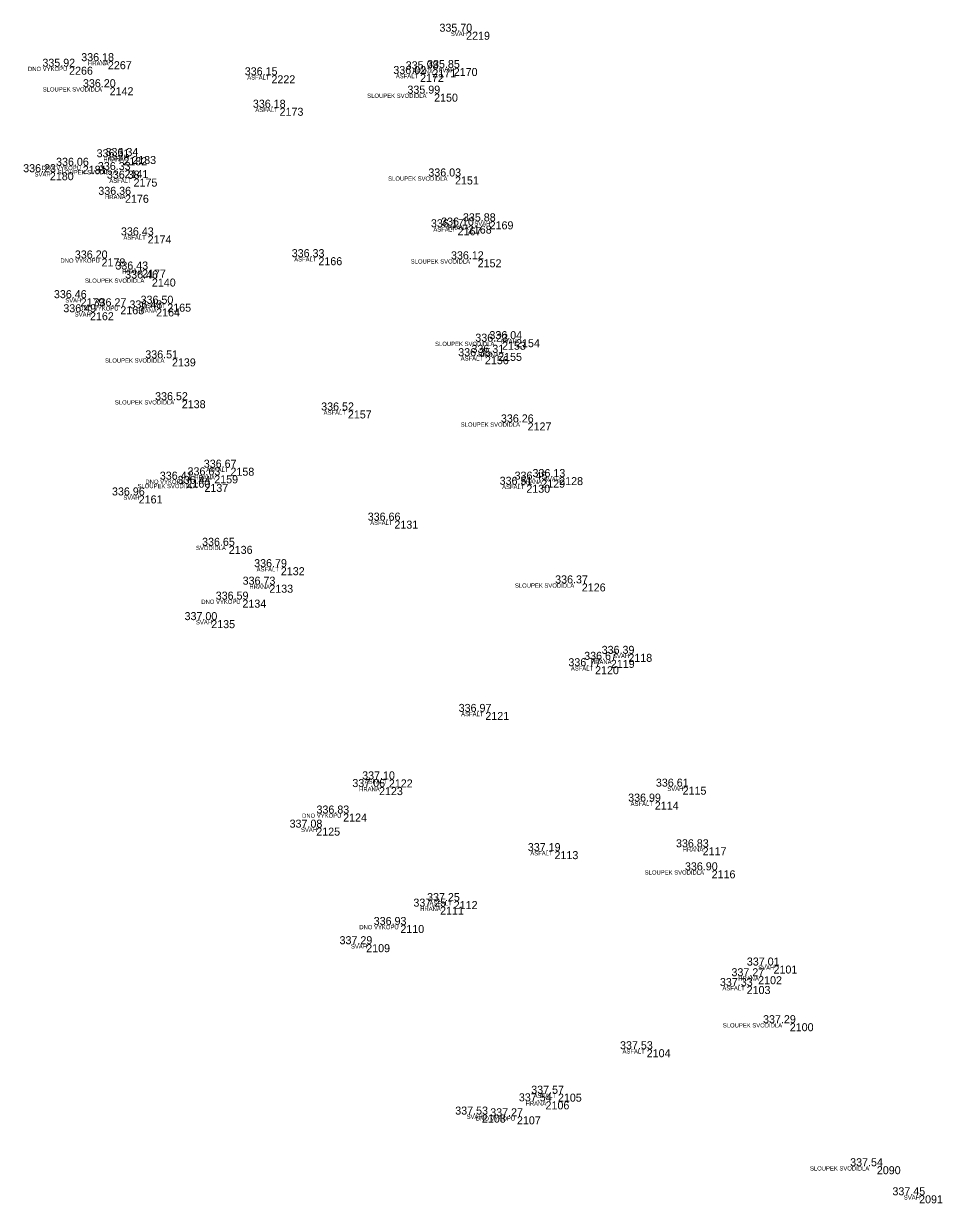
# Model space of a CAD drawing. Extents: x -597865 to -597551, y -1151663 to -1149883.
# Drawn here: x -597660.92 to -597639.39, y -1150021.29 to -1149993.66 of the extents above; entities that cross this region are included whole.
import ezdxf

# ---------------------------------------------------------------- set-up
doc = ezdxf.new("R2010")
doc.units = 0
for name, color, linetype in [('Vrstva 11', 7, 'Continuous'), ('Vrstva 12', 7, 'Continuous'), ('Vrstva 13', 7, 'Continuous'), ('Vrstva 14', 7, 'Continuous')]:
    doc.layers.add(name, color=color, linetype=linetype)

msp = doc.modelspace()

# ---------------------------------------------------------------- linework, layer by layer
at = {"layer": 'Vrstva 11'}
for p, q in [((-597650.55, -1149993.85), (-597650.55, -1149993.85)), ((-597659.85, -1149994.67), (-597659.85, -1149994.67)), ((-597658.94, -1149994.54), (-597658.94, -1149994.54)), ((-597651.34, -1149994.73), (-597651.34, -1149994.73)), ((-597650.84, -1149994.7), (-597650.84, -1149994.7)), ((-597655.11, -1149994.87), (-597655.11, -1149994.87)), ((-597651.63, -1149994.84), (-597651.63, -1149994.84)), ((-597658.9, -1149995.15), (-597658.9, -1149995.15)), ((-597651.3, -1149995.3), (-597651.3, -1149995.3)), ((-597654.92, -1149995.63), (-597654.92, -1149995.63)), ((-597658.58, -1149996.79), (-597658.58, -1149996.79)), ((-597658.37, -1149996.76), (-597658.37, -1149996.76)), ((-597660.3, -1149997.14), (-597660.3, -1149997.14)), ((-597659.53, -1149996.99), (-597659.53, -1149996.99)), ((-597658.55, -1149997.09), (-597658.55, -1149997.09)), ((-597650.81, -1149997.24), (-597650.81, -1149997.24)), ((-597658.34, -1149997.29), (-597658.34, -1149997.29)), ((-597658.54, -1149997.67), (-597658.54, -1149997.67)), ((-597650, -1149998.29), (-597650, -1149998.29)), ((-597658.01, -1149998.62), (-597658.01, -1149998.62)), ((-597650.75, -1149998.43), (-597650.75, -1149998.43)), ((-597650.51, -1149998.39), (-597650.51, -1149998.39)), ((-597659.09, -1149999.16), (-597659.09, -1149999.16)), ((-597654.01, -1149999.13), (-597654.01, -1149999.13)), ((-597650.28, -1149999.18), (-597650.28, -1149999.18)), ((-597658.14, -1149999.42), (-597658.14, -1149999.42)), ((-597657.91, -1149999.63), (-597657.91, -1149999.63)), ((-597659.58, -1150000.09), (-597659.58, -1150000.09)), ((-597658.65, -1150000.28), (-597658.65, -1150000.28)), ((-597657.55, -1150000.22), (-597657.55, -1150000.22)), ((-597659.36, -1150000.42), (-597659.36, -1150000.42)), ((-597657.81, -1150000.33), (-597657.81, -1150000.33)), ((-597649.71, -1150001.11), (-597649.71, -1150001.11)), ((-597649.38, -1150001.05), (-597649.38, -1150001.05)), ((-597649.8, -1150001.37), (-597649.8, -1150001.37)), ((-597657.44, -1150001.5), (-597657.44, -1150001.5)), ((-597650.11, -1150001.45), (-597650.11, -1150001.45)), ((-597657.21, -1150002.48), (-597657.21, -1150002.48)), ((-597653.32, -1150002.72), (-597653.32, -1150002.72)), ((-597649.11, -1150003), (-597649.11, -1150003)), ((-597656.07, -1150004.06), (-597656.07, -1150004.06)), ((-597657.1, -1150004.34), (-597657.1, -1150004.34)), ((-597656.68, -1150004.44), (-597656.68, -1150004.44)), ((-597656.45, -1150004.24), (-597656.45, -1150004.24)), ((-597648.79, -1150004.34), (-597648.79, -1150004.34)), ((-597648.37, -1150004.28), (-597648.37, -1150004.28)), ((-597658.22, -1150004.71), (-597658.22, -1150004.71)), ((-597649.14, -1150004.46), (-597649.14, -1150004.46)), ((-597652.23, -1150005.3), (-597652.23, -1150005.3)), ((-597656.11, -1150005.89), (-597656.11, -1150005.89)), ((-597654.89, -1150006.39), (-597654.89, -1150006.39)), ((-597655.16, -1150006.8), (-597655.16, -1150006.8)), ((-597647.84, -1150006.77), (-597647.84, -1150006.77)), ((-597655.79, -1150007.15), (-597655.79, -1150007.15)), ((-597656.52, -1150007.63), (-597656.52, -1150007.63)), ((-597647.16, -1150008.56), (-597647.16, -1150008.56)), ((-597646.75, -1150008.42), (-597646.75, -1150008.42)), ((-597647.53, -1150008.71), (-597647.53, -1150008.71)), ((-597650.1, -1150009.78), (-597650.1, -1150009.78)), ((-597652.59, -1150011.54), (-597652.59, -1150011.54)), ((-597652.36, -1150011.36), (-597652.36, -1150011.36)), ((-597645.48, -1150011.53), (-597645.48, -1150011.53)), ((-597646.13, -1150011.88), (-597646.13, -1150011.88)), ((-597653.43, -1150012.16), (-597653.43, -1150012.16)), ((-597654.06, -1150012.49), (-597654.06, -1150012.49)), ((-597645.01, -1150012.95), (-597645.01, -1150012.95)), ((-597648.48, -1150013.04), (-597648.48, -1150013.04)), ((-597644.8, -1150013.49), (-597644.8, -1150013.49)), ((-597651.16, -1150014.34), (-597651.16, -1150014.34)), ((-597650.84, -1150014.21), (-597650.84, -1150014.21)), ((-597652.09, -1150014.77), (-597652.09, -1150014.77)), ((-597652.89, -1150015.22), (-597652.89, -1150015.22)), ((-597643.35, -1150015.72), (-597643.35, -1150015.72)), ((-597643.71, -1150015.97), (-597643.71, -1150015.97)), ((-597643.98, -1150016.2), (-597643.98, -1150016.2)), ((-597642.97, -1150017.07), (-597642.97, -1150017.07)), ((-597646.32, -1150017.68), (-597646.32, -1150017.68)), ((-597648.4, -1150018.72), (-597648.4, -1150018.72)), ((-597648.69, -1150018.9), (-597648.69, -1150018.9)), ((-597650.18, -1150019.21), (-597650.18, -1150019.21)), ((-597649.36, -1150019.25), (-597649.36, -1150019.25)), ((-597640.93, -1150020.42), (-597640.93, -1150020.42)), ((-597639.94, -1150021.1), (-597639.94, -1150021.1))]:
    msp.add_line(p, q, dxfattribs=at)

# ---------------------------------------------------------------- texts
at = {"layer": 'Vrstva 12'}
for s, p in [('335.70 ', (-597651.175, -1149993.85)), ('335.92 ', (-597660.475, -1149994.67)), ('336.18 ', (-597659.565, -1149994.54)), ('336.15 ', (-597655.735, -1149994.87)), ('336.02 ', (-597652.255, -1149994.84)), ('335.98 ', (-597651.965, -1149994.73)), ('335.85 ', (-597651.465, -1149994.7)), ('336.20 ', (-597659.525, -1149995.15)), ('335.99 ', (-597651.925, -1149995.3)), ('336.18 ', (-597655.545, -1149995.63)), ('336.31 ', (-597659.205, -1149996.79)), ('336.34 ', (-597658.995, -1149996.76)), ('336.23 ', (-597660.925, -1149997.14)), ('336.06 ', (-597660.155, -1149996.99)), ('336.33 ', (-597659.175, -1149997.09)), ('336.38 ', (-597658.965, -1149997.29)), ('336.03 ', (-597651.435, -1149997.24)), ('336.36 ', (-597659.165, -1149997.67)), ('336.17 ', (-597651.375, -1149998.43)), ('336.10 ', (-597651.135, -1149998.39)), ('335.88 ', (-597650.625, -1149998.29)), ('336.43 ', (-597658.635, -1149998.62)), ('336.20 ', (-597659.715, -1149999.16)), ('336.33 ', (-597654.635, -1149999.13)), ('336.12 ', (-597650.905, -1149999.18)), ('336.43 ', (-597658.765, -1149999.42)), ('336.46 ', (-597658.535, -1149999.63)), ('336.46 ', (-597660.205, -1150000.09)), ('336.49 ', (-597659.985, -1150000.42)), ('336.27 ', (-597659.275, -1150000.28)), ('336.48 ', (-597658.435, -1150000.33)), ('336.50 ', (-597658.175, -1150000.22)), ('336.23 ', (-597650.335, -1150001.11)), ('336.04 ', (-597650.005, -1150001.05)), ('336.51 ', (-597658.065, -1150001.5)), ('336.35 ', (-597650.735, -1150001.45)), ('336.31 ', (-597650.425, -1150001.37)), ('336.52 ', (-597657.835, -1150002.48)), ('336.52 ', (-597653.945, -1150002.72)), ('336.26 ', (-597649.735, -1150003)), ('336.67 ', (-597656.695, -1150004.06)), ('336.41 ', (-597657.725, -1150004.34)), ('336.63 ', (-597657.075, -1150004.24)), ('336.45 ', (-597649.415, -1150004.34)), ('336.13 ', (-597648.995, -1150004.28)), ('336.44 ', (-597657.305, -1150004.44)), ('336.51 ', (-597649.765, -1150004.46)), ('336.96 ', (-597658.845, -1150004.71)), ('336.66 ', (-597652.855, -1150005.3)), ('336.65 ', (-597656.735, -1150005.89)), ('336.79 ', (-597655.515, -1150006.39)), ('336.73 ', (-597655.785, -1150006.8)), ('336.37 ', (-597648.465, -1150006.77)), ('336.59 ', (-597656.415, -1150007.15)), ('337.00 ', (-597657.145, -1150007.63)), ('336.39 ', (-597647.375, -1150008.42)), ('336.77 ', (-597648.155, -1150008.71)), ('336.67 ', (-597647.785, -1150008.56)), ('336.97 ', (-597650.725, -1150009.78)), ('337.06 ', (-597653.215, -1150011.54)), ('337.10 ', (-597652.985, -1150011.36)), ('336.61 ', (-597646.105, -1150011.53)), ('336.99 ', (-597646.755, -1150011.88)), ('336.83 ', (-597654.055, -1150012.16)), ('337.08 ', (-597654.685, -1150012.49)), ('337.19 ', (-597649.105, -1150013.04)), ('336.83 ', (-597645.635, -1150012.95)), ('336.90 ', (-597645.425, -1150013.49)), ('337.25 ', (-597651.465, -1150014.21)), ('337.25 ', (-597651.785, -1150014.34)), ('336.93 ', (-597652.715, -1150014.77)), ('337.29 ', (-597653.515, -1150015.22)), ('337.01 ', (-597643.975, -1150015.72)), ('337.33 ', (-597644.605, -1150016.2)), ('337.27 ', (-597644.335, -1150015.97)), ('337.29 ', (-597643.595, -1150017.07)), ('337.53 ', (-597646.945, -1150017.68)), ('337.57 ', (-597649.025, -1150018.72)), ('337.54 ', (-597649.315, -1150018.9)), ('337.53 ', (-597650.805, -1150019.21)), ('337.27 ', (-597649.985, -1150019.25)), ('337.54 ', (-597641.555, -1150020.42)), ('337.45 ', (-597640.565, -1150021.1))]:
    msp.add_text(s, height=0.1875, dxfattribs=at).set_placement(p)
at = {"layer": 'Vrstva 13'}
for s, p in [('2219', (-597650.55, -1149994.038)), ('2266', (-597659.85, -1149994.857)), ('2267', (-597658.94, -1149994.728)), ('2171', (-597651.34, -1149994.917)), ('2170', (-597650.84, -1149994.887)), ('2222', (-597655.11, -1149995.058)), ('2172', (-597651.63, -1149995.028)), ('2142', (-597658.9, -1149995.338)), ('2150', (-597651.3, -1149995.488)), ('2173', (-597654.92, -1149995.818)), ('2182', (-597658.58, -1149996.978)), ('2183', (-597658.37, -1149996.948)), ('2180', (-597660.3, -1149997.328)), ('2181', (-597659.53, -1149997.177)), ('2141', (-597658.55, -1149997.278)), ('2151', (-597650.81, -1149997.427)), ('2175', (-597658.34, -1149997.478)), ('2176', (-597658.54, -1149997.857)), ('2169', (-597650, -1149998.478)), ('2174', (-597658.01, -1149998.808)), ('2167', (-597650.75, -1149998.617)), ('2168', (-597650.51, -1149998.578)), ('2178', (-597659.09, -1149999.347)), ('2166', (-597654.01, -1149999.318)), ('2152', (-597650.28, -1149999.367)), ('2177', (-597658.14, -1149999.607)), ('2140', (-597657.91, -1149999.818)), ('2179', (-597659.58, -1150000.278)), ('2163', (-597658.65, -1150000.468)), ('2165', (-597657.55, -1150000.407)), ('2162', (-597659.36, -1150000.607)), ('2164', (-597657.81, -1150000.518)), ('2153', (-597649.71, -1150001.298)), ('2154', (-597649.38, -1150001.238)), ('2155', (-597649.8, -1150001.558)), ('2139', (-597657.44, -1150001.688)), ('2156', (-597650.11, -1150001.637)), ('2138', (-597657.21, -1150002.667)), ('2157', (-597653.32, -1150002.907)), ('2127', (-597649.11, -1150003.188)), ('2158', (-597656.07, -1150004.248)), ('2160', (-597657.1, -1150004.528)), ('2137', (-597656.68, -1150004.627)), ('2159', (-597656.45, -1150004.427)), ('2129', (-597648.79, -1150004.528)), ('2128', (-597648.37, -1150004.468)), ('2161', (-597658.22, -1150004.897)), ('2130', (-597649.14, -1150004.647)), ('2131', (-597652.23, -1150005.488)), ('2136', (-597656.11, -1150006.078)), ('2132', (-597654.89, -1150006.578)), ('2133', (-597655.16, -1150006.988)), ('2126', (-597647.84, -1150006.958)), ('2134', (-597655.79, -1150007.338)), ('2135', (-597656.52, -1150007.818)), ('2119', (-597647.16, -1150008.748)), ('2118', (-597646.75, -1150008.607)), ('2120', (-597647.53, -1150008.897)), ('2121', (-597650.1, -1150009.968)), ('2123', (-597652.59, -1150011.728)), ('2122', (-597652.36, -1150011.548)), ('2115', (-597645.48, -1150011.718)), ('2114', (-597646.13, -1150012.068)), ('2124', (-597653.43, -1150012.347)), ('2125', (-597654.06, -1150012.677)), ('2117', (-597645.01, -1150013.137)), ('2113', (-597648.48, -1150013.228)), ('2116', (-597644.8, -1150013.677)), ('2111', (-597651.16, -1150014.528)), ('2112', (-597650.84, -1150014.397)), ('2110', (-597652.09, -1150014.958)), ('2109', (-597652.89, -1150015.407)), ('2101', (-597643.35, -1150015.907)), ('2102', (-597643.71, -1150016.157)), ('2103', (-597643.98, -1150016.387)), ('2100', (-597642.97, -1150017.258)), ('2104', (-597646.32, -1150017.867)), ('2105', (-597648.4, -1150018.907)), ('2106', (-597648.69, -1150019.088)), ('2108', (-597650.18, -1150019.397)), ('2107', (-597649.36, -1150019.438)), ('2090', (-597640.93, -1150020.607)), ('2091', (-597639.94, -1150021.288))]:
    msp.add_text(s, height=0.1875, dxfattribs=at).set_placement(p)
at = {"layer": 'Vrstva 14'}
for s, p in [('SVAH', (-597650.908, -1149993.95)), ('DNO VYKOPU', (-597660.812, -1149994.77)), ('HRANA', (-597659.407, -1149994.64)), ('HRANA', (-597651.807, -1149994.83)), ('SVAH', (-597651.198, -1149994.8)), ('ASFALT', (-597655.677, -1149994.97)), ('ASFALT', (-597652.197, -1149994.94)), ('SLOUPEK SVODIDLA', (-597660.467, -1149995.25)), ('SLOUPEK SVODIDLA', (-597652.867, -1149995.4)), ('ASFALT', (-597655.487, -1149995.73)), ('HRANA', (-597659.047, -1149996.89)), ('ASFALT', (-597658.937, -1149996.86)), ('SVAH', (-597660.658, -1149997.24)), ('DNO VYKOPU', (-597660.493, -1149997.09)), ('SLOUPEK SVODIDLA', (-597660.117, -1149997.19)), ('SLOUPEK SVODIDLA', (-597652.377, -1149997.34)), ('ASFALT', (-597658.907, -1149997.39)), ('HRANA', (-597659.007, -1149997.77)), ('SVAH', (-597650.358, -1149998.39)), ('ASFALT', (-597658.577, -1149998.72)), ('ASFALT', (-597651.317, -1149998.53)), ('HRANA', (-597650.977, -1149998.49)), ('DNO VYKOPU', (-597660.052, -1149999.26)), ('ASFALT', (-597654.577, -1149999.23)), ('SLOUPEK SVODIDLA', (-597651.847, -1149999.28)), ('HRANA', (-597658.607, -1149999.52)), ('SLOUPEK SVODIDLA', (-597659.477, -1149999.73)), ('SVAH', (-597659.938, -1150000.19)), ('DNO VYKOPU', (-597659.613, -1150000.38)), ('ASFALT', (-597658.117, -1150000.32)), ('SVAH', (-597659.718, -1150000.52)), ('HRANA', (-597658.277, -1150000.43)), ('SLOUPEK SVODIDLA', (-597651.277, -1150001.21)), ('SVAH', (-597649.738, -1150001.15)), ('HRANA', (-597650.267, -1150001.47)), ('SLOUPEK SVODIDLA', (-597659.007, -1150001.6)), ('ASFALT', (-597650.677, -1150001.55)), ('SLOUPEK SVODIDLA', (-597658.777, -1150002.58)), ('ASFALT', (-597653.887, -1150002.82)), ('SLOUPEK SVODIDLA', (-597650.677, -1150003.1)), ('ASFALT', (-597656.637, -1150004.16)), ('SLOUPEK SVODIDLA', (-597658.247, -1150004.54)), ('DNO VYKOPU', (-597658.062, -1150004.44)), ('HRANA', (-597656.917, -1150004.34)), ('HRANA', (-597649.257, -1150004.44)), ('SVAH', (-597648.728, -1150004.38)), ('SVAH', (-597658.578, -1150004.81)), ('ASFALT', (-597649.707, -1150004.56)), ('ASFALT', (-597652.797, -1150005.4)), ('SVODIDLA', (-597656.877, -1150005.99)), ('ASFALT', (-597655.457, -1150006.49)), ('HRANA', (-597655.627, -1150006.9)), ('SLOUPEK SVODIDLA', (-597649.407, -1150006.87)), ('DNO VYKOPU', (-597656.753, -1150007.25)), ('SVAH', (-597656.878, -1150007.73)), ('HRANA', (-597647.627, -1150008.66)), ('SVAH', (-597647.108, -1150008.52)), ('ASFALT', (-597648.097, -1150008.81)), ('ASFALT', (-597650.667, -1150009.88)), ('HRANA', (-597653.057, -1150011.64)), ('ASFALT', (-597652.927, -1150011.46)), ('SVAH', (-597645.838, -1150011.63)), ('ASFALT', (-597646.697, -1150011.98)), ('DNO VYKOPU', (-597654.392, -1150012.26)), ('SVAH', (-597654.418, -1150012.59)), ('HRANA', (-597645.477, -1150013.05)), ('ASFALT', (-597649.047, -1150013.14)), ('SLOUPEK SVODIDLA', (-597646.367, -1150013.59)), ('HRANA', (-597651.627, -1150014.44)), ('ASFALT', (-597651.407, -1150014.31)), ('DNO VYKOPU', (-597653.052, -1150014.87)), ('SVAH', (-597653.248, -1150015.32)), ('SVAH', (-597643.708, -1150015.82)), ('HRANA', (-597644.177, -1150016.07)), ('ASFALT', (-597644.547, -1150016.3)), ('SLOUPEK SVODIDLA', (-597644.537, -1150017.17)), ('ASFALT', (-597646.887, -1150017.78)), ('ASFALT', (-597648.967, -1150018.82)), ('HRANA', (-597649.157, -1150019)), ('SVAH', (-597650.538, -1150019.31)), ('DNO VYKOPU', (-597650.323, -1150019.35)), ('SLOUPEK SVODIDLA', (-597642.497, -1150020.52)), ('SVAH', (-597640.298, -1150021.2))]:
    msp.add_text(s, height=0.1, dxfattribs=at).set_placement(p)

doc.saveas('drawing.dxf')
